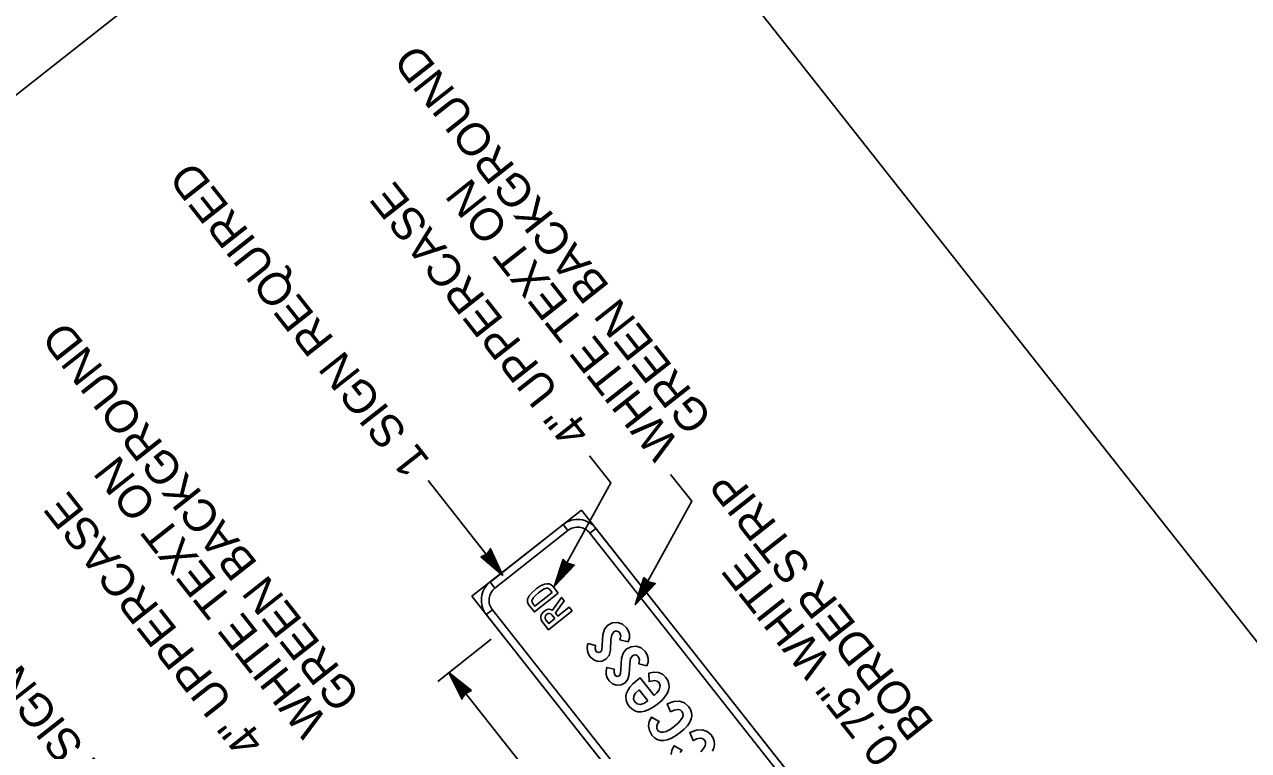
# Model space of a CAD drawing. Extents: x 672126 to 673696, y 1673540 to 1674900.
# Drawn here: x 672217.5 to 672375.5, y 1674682.5 to 1674776.3 of the extents above; entities that cross this region are included whole.
import ezdxf

# ---------------------------------------------------------------- set-up
doc = ezdxf.new("R2010")
doc.units = 0
for name, color, linetype in [('61', 7, 'Continuous'), ('C-ANNO-SYMB', 7, 'Continuous'), ('Level 1', 7, 'Continuous')]:
    doc.layers.add(name, color=color, linetype=linetype)

msp = doc.modelspace()

# ---------------------------------------------------------------- linework, layer by layer
at = {"layer": '61'}
msp.add_lwpolyline([(672517.13, 1674725.06), (672386.09, 1674891.28), (672285.59, 1674812.06), (672416.63, 1674645.83)], close=True, dxfattribs=at)
at = {"layer": 'C-ANNO-SYMB'}
for p, q in [((672289.4, 1674713.6), (672275.26, 1674702.46)), ((672289.4, 1674713.6), (672333.97, 1674657.06)), ((672287.04, 1674711.74), (672287.66, 1674710.96)), ((672290.47, 1674710.62), (672291.26, 1674711.24)), ((672278.24, 1674703.53), (672277.62, 1674704.31)), ((672275.26, 1674702.46), (672319.84, 1674645.91)), ((672277.12, 1674700.1), (672277.91, 1674700.72))]:
    msp.add_line(p, q, dxfattribs=at)
for points in [[(672287.66, 1674710.96), (672278.24, 1674703.53), (672277.62, 1674704.31), (672287.04, 1674711.74), (672287.66, 1674710.96), (672287.66, 1674710.96)], [(672331.33, 1674658.79), (672290.47, 1674710.62), (672291.26, 1674711.24), (672332.12, 1674659.41), (672331.33, 1674658.79), (672331.33, 1674658.79)], [(672277.91, 1674700.72), (672318.77, 1674648.89), (672317.98, 1674648.27), (672277.12, 1674700.1), (672277.91, 1674700.72), (672277.91, 1674700.72)], [(672295.43, 1674696.57), (672295.59, 1674697.05), (672295.61, 1674697.51), (672295.48, 1674697.97), (672295.2, 1674698.41), (672294.68, 1674698.88), (672294.04, 1674699.09), (672293.38, 1674699.03), (672292.76, 1674698.7), (672292.36, 1674698.21), (672292.14, 1674697.5), (672292.08, 1674696.13), (672292.03, 1674695.56), (672291.89, 1674695.28), (672291.58, 1674695.19), (672291.31, 1674695.33), (672291.19, 1674695.7), (672291.21, 1674696.12), (672290.23, 1674696.36), (672290.15, 1674695.88), (672290.18, 1674695.43), (672290.31, 1674695.01), (672290.53, 1674694.64), (672290.98, 1674694.25), (672291.52, 1674694.06), (672292.09, 1674694.1), (672292.6, 1674694.37), (672292.97, 1674694.83), (672293.15, 1674695.5), (672293.21, 1674696.87), (672293.32, 1674697.49), (672293.57, 1674697.87), (672293.75, 1674697.96), (672293.95, 1674697.97), (672294.15, 1674697.91), (672294.3, 1674697.77), (672294.47, 1674697.34), (672294.37, 1674696.83)], [(672297.86, 1674693.5), (672298.02, 1674693.97), (672298.03, 1674694.44), (672297.9, 1674694.89), (672297.62, 1674695.34), (672297.11, 1674695.8), (672296.47, 1674696.01), (672295.8, 1674695.95), (672295.18, 1674695.62), (672294.79, 1674695.13), (672294.57, 1674694.43), (672294.5, 1674693.05), (672294.45, 1674692.49), (672294.31, 1674692.2), (672294.01, 1674692.11), (672293.74, 1674692.25), (672293.61, 1674692.63), (672293.64, 1674693.04), (672292.66, 1674693.28), (672292.58, 1674692.8), (672292.6, 1674692.35), (672292.73, 1674691.94), (672292.96, 1674691.56), (672293.4, 1674691.17), (672293.94, 1674690.99), (672294.51, 1674691.02), (672295.03, 1674691.29), (672295.39, 1674691.75), (672295.58, 1674692.42), (672295.64, 1674693.79), (672295.75, 1674694.42), (672295.99, 1674694.79), (672296.17, 1674694.88), (672296.38, 1674694.89), (672296.57, 1674694.83), (672296.73, 1674694.69), (672296.9, 1674694.26), (672296.8, 1674693.75)], [(672300.88, 1674687.53), (672301.37, 1674687.77), (672301.78, 1674687.86), (672302.12, 1674687.8), (672302.37, 1674687.59), (672302.49, 1674687.37), (672302.51, 1674687.12), (672302.43, 1674686.83), (672302.24, 1674686.52), (672301.88, 1674686.08), (672301.38, 1674685.64), (672300.84, 1674685.27), (672300.32, 1674685.02), (672299.98, 1674684.92), (672299.69, 1674684.9), (672299.45, 1674684.98), (672299.26, 1674685.14), (672299.13, 1674685.4), (672299.12, 1674685.67), (672299.22, 1674685.97), (672299.45, 1674686.29), (672298.45, 1674686.87), (672298.13, 1674686.31), (672298.04, 1674685.71), (672298.17, 1674685.11), (672298.5, 1674684.54), (672298.83, 1674684.2), (672299.19, 1674683.97), (672299.6, 1674683.84), (672300.03, 1674683.83), (672300.51, 1674683.92), (672301.02, 1674684.13), (672301.56, 1674684.44), (672302.15, 1674684.86), (672302.67, 1674685.31), (672303.08, 1674685.75), (672303.38, 1674686.19), (672303.57, 1674686.62), (672303.65, 1674687.04), (672303.61, 1674687.45), (672303.47, 1674687.85), (672303.21, 1674688.25), (672302.68, 1674688.72), (672302.06, 1674688.94), (672301.32, 1674688.89), (672300.48, 1674688.58)]]:
    msp.add_lwpolyline(points, close=True, dxfattribs=at)
for points in [[(672286.4, 1674702.86), (672285.69, 1674703.76), (672285.49, 1674703.95), (672285.25, 1674704.06), (672284.96, 1674704.08), (672284.63, 1674704.03), (672284.11, 1674703.82), (672283.59, 1674703.47), (672283.03, 1674702.97), (672282.65, 1674702.51), (672282.45, 1674702.08), (672282.43, 1674701.69), (672282.51, 1674701.5), (672282.66, 1674701.28), (672283.32, 1674700.44), (672286.4, 1674702.86)], [(672285.62, 1674702.94), (672283.4, 1674701.18), (672283.11, 1674701.54), (672283.02, 1674701.71), (672283.01, 1674701.9), (672283.07, 1674702.1), (672283.2, 1674702.31), (672283.46, 1674702.58), (672283.86, 1674702.92), (672284.21, 1674703.19), (672284.52, 1674703.39), (672284.76, 1674703.49), (672284.93, 1674703.52), (672285.08, 1674703.5), (672285.21, 1674703.43), (672285.32, 1674703.32), (672285.62, 1674702.94)], [(672288.21, 1674700.57), (672287.83, 1674701.05), (672286.36, 1674699.9), (672286.04, 1674700.31), (672287.19, 1674701.87), (672286.84, 1674702.31), (672285.67, 1674700.67), (672285.41, 1674700.77), (672285.13, 1674700.78), (672284.87, 1674700.71), (672284.62, 1674700.56), (672284.44, 1674700.4), (672284.31, 1674700.23), (672284.22, 1674700.05), (672284.16, 1674699.86), (672284.15, 1674699.66), (672284.19, 1674699.46), (672284.27, 1674699.26), (672284.4, 1674699.06), (672285.13, 1674698.14), (672288.21, 1674700.57)], [(672285.96, 1674699.58), (672285.17, 1674698.96), (672284.81, 1674699.41), (672284.72, 1674699.59), (672284.7, 1674699.78), (672284.76, 1674699.96), (672284.9, 1674700.12), (672285.09, 1674700.23), (672285.27, 1674700.25), (672285.43, 1674700.19), (672285.59, 1674700.05), (672285.96, 1674699.58)], [(672298.78, 1674689.64), (672296.98, 1674691.93), (672296.55, 1674691.6), (672296.05, 1674691.16), (672295.66, 1674690.73), (672295.37, 1674690.3), (672295.19, 1674689.88), (672295.13, 1674689.46), (672295.16, 1674689.05), (672295.32, 1674688.65), (672295.57, 1674688.25), (672295.9, 1674687.91), (672296.27, 1674687.68), (672296.68, 1674687.55), (672297.11, 1674687.54), (672297.59, 1674687.64), (672298.1, 1674687.84), (672298.65, 1674688.15), (672299.24, 1674688.58), (672299.76, 1674689.02), (672300.17, 1674689.47), (672300.46, 1674689.9), (672300.65, 1674690.33), (672300.73, 1674690.74), (672300.69, 1674691.16), (672300.54, 1674691.57), (672300.28, 1674691.97), (672299.84, 1674692.39), (672299.33, 1674692.63), (672298.75, 1674692.68), (672298.1, 1674692.54), (672298.14, 1674691.45), (672298.81, 1674691.58), (672299.17, 1674691.51), (672299.44, 1674691.3), (672299.57, 1674690.9), (672299.42, 1674690.4), (672299.15, 1674690.01), (672298.78, 1674689.64)], [(672297.96, 1674688.95), (672297.44, 1674688.63), (672296.99, 1674688.5), (672296.61, 1674688.57), (672296.3, 1674688.82), (672296.13, 1674689.18), (672296.16, 1674689.56), (672296.39, 1674689.96), (672296.83, 1674690.38), (672297.96, 1674688.95)], [(672306.3, 1674682.48), (672306.49, 1674682.91), (672306.57, 1674683.33), (672306.53, 1674683.74), (672306.39, 1674684.15), (672306.13, 1674684.55), (672305.61, 1674685.02), (672304.98, 1674685.23), (672304.25, 1674685.18), (672303.41, 1674684.88), (672303.8, 1674683.83), (672304.29, 1674684.06), (672304.7, 1674684.15), (672305.04, 1674684.09), (672305.3, 1674683.89), (672305.41, 1674683.66), (672305.43, 1674683.41), (672305.35, 1674683.13), (672305.16, 1674682.82), (672304.8, 1674682.38)], [(672302.15, 1674682.27), (672302.37, 1674682.59), (672301.37, 1674683.16), (672301.05, 1674682.6), (672300.96, 1674682.01)]]:
    msp.add_lwpolyline(points, dxfattribs=at)
for centre, radius, start, end in [((672288.9, 1674709.39), 3, 38.2506, 128.2508), ((672288.9, 1674709.39), 2, 38.2506, 128.2508), ((672279.48, 1674701.96), 3, 128.2505, 218.2508), ((672279.48, 1674701.96), 2, 128.2505, 218.2508)]:
    msp.add_arc(centre, radius, start, end, dxfattribs=at)
at = {"layer": 'Level 1'}
for p, q in [((672125.9, 1674695.83), (672385.43, 1674900.44)), ((672279.27, 1674705.17), (672269.61, 1674717.42)), ((672276.86, 1674707.52), (672277.57, 1674708.19)), ((672276.99, 1674707.65), (672277.57, 1674708.19)), ((672276.99, 1674707.56), (672277.51, 1674708.01)), ((672277.13, 1674707.86), (672277.62, 1674708.52)), ((672277.18, 1674707.92), (672277.49, 1674708.16)), ((672277.49, 1674708.16), (672277.69, 1674708.47)), ((672277.51, 1674708.01), (672278.22, 1674706.48)), ((672277.62, 1674708.52), (672277.55, 1674708.3)), ((672277.55, 1674708.3), (672277.65, 1674708.31)), ((672277.57, 1674708.19), (672278.55, 1674706.04)), ((672277.57, 1674708.19), (672278.68, 1674705.97)), ((672277.64, 1674708.66), (672279.27, 1674705.17)), ((672277.65, 1674708.31), (672279.01, 1674705.43)), ((672277.69, 1674708.47), (672278.92, 1674705.6)), ((672276.41, 1674707.55), (672277.18, 1674707.92)), ((672279.27, 1674705.17), (672276.41, 1674707.55)), ((672276.56, 1674707.53), (672277.13, 1674707.86)), ((672279.04, 1674705.39), (672276.56, 1674707.53)), ((672276.73, 1674707.52), (672276.99, 1674707.65)), ((672278.77, 1674705.75), (672276.73, 1674707.52)), ((672278.55, 1674706.04), (672276.86, 1674707.52)), ((672278.68, 1674705.97), (672276.99, 1674707.56)), ((672277.4, 1674707.93), (672277.12, 1674707.56)), ((672277.12, 1674707.56), (672277.87, 1674707.04)), ((672277.14, 1674707.5), (672277.47, 1674707.85)), ((672278.22, 1674706.48), (672277.14, 1674707.5)), ((672277.26, 1674707.46), (672277.41, 1674707.74)), ((672277.96, 1674706.88), (672277.26, 1674707.46)), ((672277.34, 1674707.49), (672277.41, 1674707.57)), ((672277.67, 1674707.22), (672277.34, 1674707.49)), ((672277.41, 1674707.57), (672277.4, 1674707.93)), ((672277.41, 1674707.74), (672277.67, 1674707.22)), ((672277.47, 1674707.85), (672277.96, 1674706.88)), ((672277.87, 1674707.04), (672277.97, 1674706.78)), ((672285.9, 1674703.73), (672287.02, 1674707.28)), ((672288.55, 1674706.53), (672285.9, 1674703.73)), ((672286.02, 1674704.03), (672287.05, 1674707.14)), ((672288.18, 1674706.43), (672286.04, 1674704.07)), ((672288.35, 1674706.45), (672286.16, 1674704.22)), ((672286.25, 1674704.41), (672287.11, 1674706.98)), ((672286.41, 1674704.58), (672287.25, 1674706.75)), ((672288.05, 1674706.45), (672286.41, 1674704.58)), ((672286.44, 1674704.73), (672287.16, 1674706.86)), ((672288.05, 1674706.45), (672286.44, 1674704.73)), ((672286.72, 1674705.2), (672287.25, 1674706.59)), ((672287.86, 1674706.44), (672286.72, 1674705.2)), ((672286.98, 1674705.59), (672287.26, 1674706.46)), ((672287.69, 1674706.42), (672286.98, 1674705.59)), ((672287.02, 1674707.28), (672287.66, 1674706.71)), ((672287.05, 1674707.14), (672287.57, 1674706.73)), ((672287.3, 1674706.62), (672287.1, 1674705.73)), ((672287.11, 1674706.98), (672287.33, 1674706.78)), ((672287.16, 1674706.86), (672288.05, 1674706.45)), ((672287.57, 1674706.42), (672287.19, 1674705.99)), ((672287.25, 1674706.75), (672287.86, 1674706.44)), ((672287.25, 1674706.59), (672287.69, 1674706.42)), ((672287.26, 1674706.46), (672287.57, 1674706.42)), ((672287.74, 1674706.51), (672287.3, 1674706.62)), ((672287.33, 1674706.78), (672288.05, 1674706.45)), ((672287.41, 1674706.37), (672287.74, 1674706.51)), ((672287.57, 1674706.73), (672288.37, 1674706.53)), ((672287.66, 1674706.71), (672287.99, 1674706.51)), ((672287.99, 1674706.51), (672288.35, 1674706.45)), ((672288.14, 1674706.51), (672288.18, 1674706.43)), ((672286.23, 1674704.18), (672286.82, 1674704.86)), ((672286.82, 1674704.86), (672286.25, 1674704.41)), ((672286.9, 1674705.55), (672286.69, 1674705.09)), ((672286.69, 1674705.09), (672287.02, 1674705.45)), ((672287.1, 1674705.73), (672286.9, 1674705.55)), ((672287.19, 1674705.99), (672287.31, 1674706.4)), ((672287.31, 1674706.4), (672287.41, 1674706.37)), ((672296.35, 1674701.34), (672297.46, 1674704.89)), ((672297.46, 1674704.89), (672298.1, 1674704.33)), ((672299, 1674704.14), (672296.35, 1674701.34)), ((672296.47, 1674701.64), (672297.5, 1674704.75)), ((672298.63, 1674704.04), (672296.49, 1674701.69)), ((672298.8, 1674704.06), (672296.61, 1674701.83)), ((672296.69, 1674702.03), (672297.56, 1674704.59)), ((672296.86, 1674702.2), (672297.69, 1674704.36)), ((672298.49, 1674704.06), (672296.86, 1674702.2)), ((672296.88, 1674702.34), (672297.61, 1674704.47)), ((672298.49, 1674704.06), (672296.88, 1674702.34)), ((672297.17, 1674702.81), (672297.7, 1674704.2)), ((672298.31, 1674704.05), (672297.17, 1674702.81)), ((672297.55, 1674703.35), (672297.35, 1674703.16)), ((672297.43, 1674703.2), (672297.71, 1674704.07)), ((672298.14, 1674704.03), (672297.43, 1674703.2)), ((672297.5, 1674704.75), (672298.02, 1674704.34)), ((672297.75, 1674704.24), (672297.55, 1674703.35)), ((672297.56, 1674704.59), (672297.78, 1674704.4)), ((672297.61, 1674704.47), (672298.49, 1674704.06)), ((672298.02, 1674704.04), (672297.64, 1674703.6)), ((672297.64, 1674703.6), (672297.76, 1674704.01)), ((672297.69, 1674704.36), (672298.31, 1674704.05)), ((672297.7, 1674704.2), (672298.14, 1674704.03)), ((672297.71, 1674704.07), (672298.02, 1674704.04)), ((672298.19, 1674704.12), (672297.75, 1674704.24)), ((672297.76, 1674704.01), (672297.86, 1674703.98)), ((672297.78, 1674704.4), (672298.49, 1674704.06)), ((672297.86, 1674703.98), (672298.19, 1674704.12)), ((672298.02, 1674704.34), (672298.82, 1674704.14)), ((672298.1, 1674704.33), (672298.44, 1674704.12)), ((672298.44, 1674704.12), (672298.8, 1674704.06)), ((672298.59, 1674704.12), (672298.63, 1674704.04)), ((672296.68, 1674701.79), (672297.27, 1674702.47)), ((672297.27, 1674702.47), (672296.69, 1674702.03)), ((672297.35, 1674703.16), (672297.13, 1674702.71)), ((672297.13, 1674702.71), (672297.47, 1674703.06)), ((672277.75, 1674696.92), (672270.85, 1674691.48)), ((672274, 1674689.15), (672272.29, 1674692.62)), ((672272.29, 1674692.62), (672275.2, 1674690.29)), ((672288.28, 1674672.4), (672272.33, 1674692.64)), ((672272.65, 1674692.19), (672272.53, 1674692.4)), ((672272.53, 1674692.4), (672275.05, 1674690.31)), ((672273.98, 1674689.51), (672272.56, 1674692.36)), ((672272.56, 1674692.36), (672272.59, 1674692.15)), ((672273.94, 1674689.35), (672272.65, 1674692.19)), ((672272.59, 1674692.15), (672273.01, 1674691.35)), ((672273.01, 1674691.35), (672272.8, 1674692.05)), ((672272.8, 1674692.05), (672274.88, 1674690.31)), ((672274.05, 1674689.63), (672272.9, 1674691.83)), ((672272.9, 1674691.83), (672274.62, 1674690.27)), ((672274.05, 1674689.63), (672273.03, 1674691.76)), ((672273.03, 1674691.76), (672274.75, 1674690.31)), ((672273.63, 1674691.03), (672273.28, 1674691.39)), ((672273.28, 1674691.39), (672273.49, 1674690.95)), ((672274.11, 1674689.81), (672273.37, 1674691.32)), ((672273.37, 1674691.32), (672274.47, 1674690.33)), ((672273.73, 1674690.77), (672273.63, 1674691.03)), ((672274.15, 1674689.97), (672273.64, 1674690.93)), ((672273.64, 1674690.93), (672274.35, 1674690.36)), ((672274.49, 1674690.27), (672273.73, 1674690.77)), ((672274.2, 1674690.08), (672273.93, 1674690.6)), ((672273.93, 1674690.6), (672274.27, 1674690.33)), ((672274.13, 1674689.66), (672273.94, 1674689.35)), ((672274.08, 1674689.52), (672273.98, 1674689.51)), ((672274.49, 1674689.97), (672274.01, 1674689.3)), ((672274.75, 1674690.31), (672274.05, 1674689.63)), ((672274.62, 1674690.18), (672274.05, 1674689.63)), ((672274.62, 1674690.27), (672274.11, 1674689.81)), ((672274.44, 1674689.9), (672274.13, 1674689.66)), ((672274.47, 1674690.33), (672274.15, 1674689.97)), ((672274.35, 1674690.36), (672274.2, 1674690.08)), ((672274.27, 1674690.33), (672274.21, 1674690.25)), ((672274.21, 1674690.25), (672274.22, 1674689.89)), ((672274.22, 1674689.89), (672274.49, 1674690.27)), ((672275.2, 1674690.29), (672274.44, 1674689.9)), ((672275.05, 1674690.31), (672274.49, 1674689.97)), ((672274.88, 1674690.31), (672274.62, 1674690.18))]:
    msp.add_line(p, q, dxfattribs=at)
for points in [[(672287.04, 1674705.94), (672293.2, 1674717.11), (672290.45, 1674720.6)], [(672297.49, 1674703.55), (672303.65, 1674714.73), (672300.9, 1674718.21)]]:
    msp.add_lwpolyline(points, dxfattribs=at)

# ---------------------------------------------------------------- texts
for s, p in [('GREEN BACKGROUND', (672306.48, 1674725.56)), ('1 SIGN REQUIRED', (672269.97, 1674719.96)), ('4" UPPERCASE', (672290.77, 1674723.81)), ('WHITE TEXT ON', (672302.18, 1674722.18)), ('GREEN BACKGROUND', (672261.06, 1674689.76)), ('2 SIGNS REQUIRED', (672228.25, 1674679.47)), ('WHITE TEXT ON', (672256.77, 1674686.38)), ('4" UPPERCASE', (672248.68, 1674683.79)), ('BORDER STRIP', (672335.04, 1674686.06)), ('0.75" WHITE ', (672330.75, 1674682.67))]:
    msp.add_text(s, height=4.2, rotation=128.2505, dxfattribs=at).set_placement(p)

doc.saveas('drawing.dxf')
